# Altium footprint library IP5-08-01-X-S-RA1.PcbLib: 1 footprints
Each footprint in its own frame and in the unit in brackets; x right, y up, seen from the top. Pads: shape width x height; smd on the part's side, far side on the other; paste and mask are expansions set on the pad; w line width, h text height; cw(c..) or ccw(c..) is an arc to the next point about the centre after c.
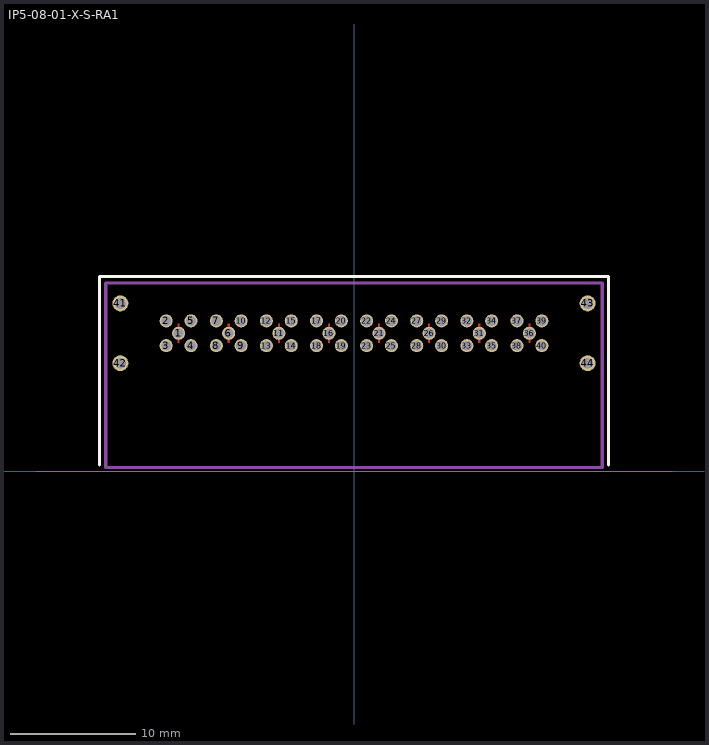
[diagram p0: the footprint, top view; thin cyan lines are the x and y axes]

## IP5-08-01-X-S-RA1 [mil]
pads (44):
  round 41 hole 31 mask+2: 1(-551.25,434) 6(-393.75,434) 11(-236.25,434) 16(-78.75,434) 21(78.75,434) 26(236.25,434) 31(393.75,434) 36(551.25,434)
  round 41 hole 31 mask+3: 2(-590.25,473) 3(-590.25,395) 4(-512.25,395) 5(-512.25,473) 7(-432.75,473) 8(-432.75,395) 9(-354.75,395) 10(-354.75,473) 12(-275.25,473) 13(-275.25,395) 14(-197.25,395) 15(-197.25,473) 17(-117.75,473) 18(-117.75,395) 19(-39.75,395) 20(-39.75,473) 22(39.75,473) 23(39.75,395) 24(117.75,473) 25(117.75,395) 27(197.25,473) 28(197.25,395) 29(275.25,473) 30(275.25,395) 32(354.75,473) 33(354.75,395) 34(432.75,473) 35(432.75,395) 37(512.25,473) 38(512.25,395) 39(590.25,473) 40(590.25,395)
  round 50 hole 34 mask+3: 41(-734.25,528) 42(-734.25,340) 43(734.25,528) 44(734.25,340)
Top Layer:
  region: 548.75,425.01 553.75,425.01 553.75,404 548.75,404
  region: 548.75,464 553.75,464 553.75,434 548.75,434
  region: 391.25,425.01 396.25,425.01 396.25,404 391.25,404
  region: 391.25,464 396.25,464 396.25,434 391.25,434
  region: 233.75,425.01 238.75,425.01 238.75,404 233.75,404
  region: 233.75,464 238.75,464 238.75,434 233.75,434
  region: 76.25,425.01 81.25,425.01 81.25,404 76.25,404
  region: 76.25,464 81.25,464 81.25,434 76.25,434
  region: -81.25,425.01 -76.25,425.01 -76.25,404 -81.25,404
  region: -81.25,464 -76.25,464 -76.25,434 -81.25,434
  region: -238.75,425.01 -233.75,425.01 -233.75,404 -238.75,404
  region: -238.75,464 -233.75,464 -233.75,434 -238.75,434
  region: -396.25,425.01 -391.25,425.01 -391.25,404 -396.25,404
  region: -396.25,464 -391.25,464 -391.25,434 -396.25,434
  region: -553.75,425.01 -548.75,425.01 -548.75,404 -553.75,404
  region: -553.75,464 -548.75,464 -548.75,434 -553.75,434
Top Overlay:
  lines w10: -800.25,20 -800.25,612 800.25,612 800.25,20
Top Paste:
  drawing of 52 lines, arcs and shapes, not listed
Bottom Paste:
  drawing of 44 lines, arcs and shapes, not listed
Top Solder:
  region: 546.75,422.94 555.75,422.94 555.75,402 546.75,402
  region: 546.75,466 555.75,466 555.75,424 546.75,424
  region: 389.25,422.94 398.25,422.94 398.25,402 389.25,402
  region: 389.25,466 398.25,466 398.25,424 389.25,424
  region: 231.75,422.94 240.75,422.94 240.75,402 231.75,402
  region: 231.75,466 240.75,466 240.75,424 231.75,424
  region: 74.25,422.94 83.25,422.94 83.25,402 74.25,402
  region: 74.25,466 83.25,466 83.25,424 74.25,424
  region: -83.25,422.94 -74.25,422.94 -74.25,402 -83.25,402
  region: -83.25,466 -74.25,466 -74.25,424 -83.25,424
  region: -240.75,422.94 -231.75,422.94 -231.75,402 -240.75,402
  region: -240.75,466 -231.75,466 -231.75,424 -240.75,424
  region: -398.25,422.94 -389.25,422.94 -389.25,402 -398.25,402
  region: -398.25,466 -389.25,466 -389.25,424 -398.25,424
  region: -555.75,422.94 -546.75,422.94 -546.75,402 -555.75,402
  region: -555.75,466 -546.75,466 -546.75,424 -555.75,424
Mechanical 1:
  lines w10: -780.25,12 -780.25,592 780.25,592 780.25,12 -780.25,12
  text "J1" at -17.57,116.25 h30
Mechanical 16:
  lines w0.1: -1000,0 1000,0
